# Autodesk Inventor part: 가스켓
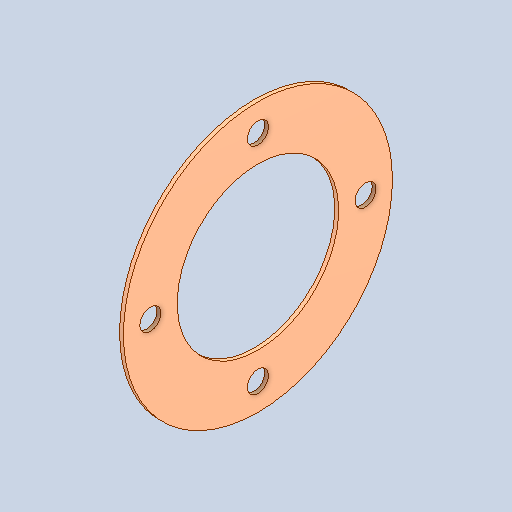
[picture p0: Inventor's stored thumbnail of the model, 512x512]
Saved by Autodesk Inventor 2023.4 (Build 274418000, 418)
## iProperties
Created: 2024-09
Part Number: 가스켓
Material: 스테인리스스틸
Document SubType Name: Modeling
Designer: 11
Density: 8 g/cm^3
Appearance: 기본값
Author: jhkim
Sending System: Autodesk Inventor 2025
Preprocessor: ST-DEVELOPER v20
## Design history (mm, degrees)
node "가스켓1"
node "솔리드2"
node "솔리드1"
